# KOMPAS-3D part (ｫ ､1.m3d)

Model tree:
1. Эскиз:1
2. Операция выдавливания:1
     Расстояние 1 = 52
3. Эскиз:2
4. Вырезать элемент выдавливания:1
     Расстояние 1 = 120
5. Эскиз:3
6. Вырезать элемент выдавливания:2
     Расстояние 1 = 120
7. Эскиз:4
8. Вырезать элемент выдавливания:3
     Расстояние 1 = 3; Угол 1 = 18
9. Эскиз:5
10. Вырезать элемент выдавливания:4
     Расстояние 1 = 2
